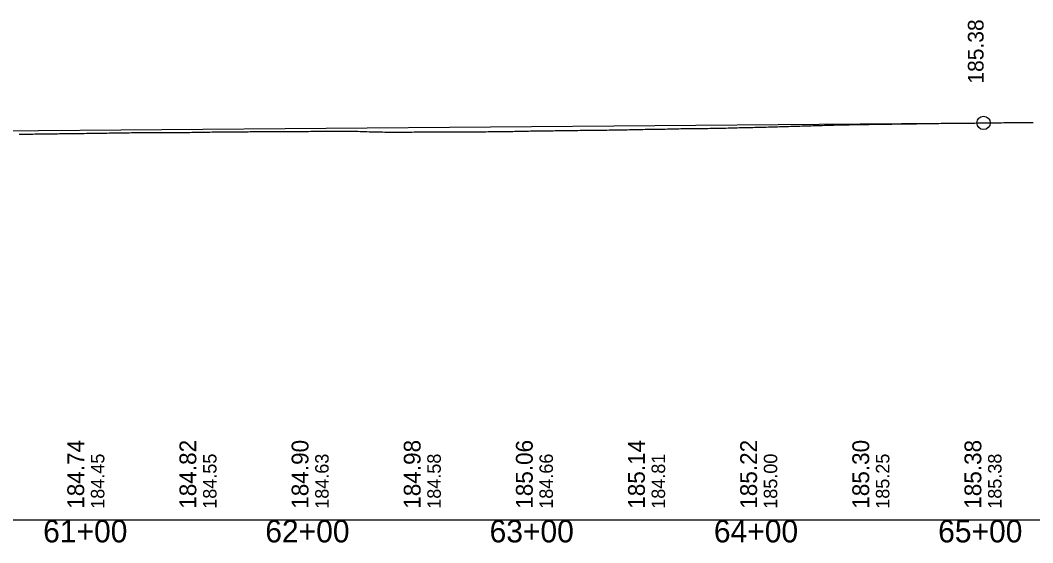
# Model space of a CAD drawing. Extents: x 69 to 2003113, y 512 to 837401.
# Drawn here: x 1893448 to 1893899.5, y 820540 to 820772.8 of the extents above; entities that cross this region are included whole.
import ezdxf

# ---------------------------------------------------------------- set-up
doc = ezdxf.new("R2010")
doc.units = 0
for name, color, linetype in [('BR_BORDER LINES', 7, 'Continuous'), ('BR_CENTER LINE BASELINE', 7, 'Continuous'), ('BR_CONCRETE', 7, 'Continuous'), ('BR_GRID LINES', 7, 'Continuous'), ('BR_TEXT', 7, 'Continuous'), ('RD_HC_Points', 7, 'Continuous'), ('RD_SHT_ID', 7, 'Continuous'), ('RD_SHT_IplotShp', 7, 'Continuous')]:
    doc.layers.add(name, color=color, linetype=linetype)

msp = doc.modelspace()

# ---------------------------------------------------------------- linework, layer by layer
at = {"layer": 'BR_BORDER LINES'}
msp.add_line((1889077.53, 820550.13), (1895477.53, 820550.13), dxfattribs=at)
at = {"layer": 'BR_CENTER LINE BASELINE'}
msp.add_circle((1893877.53, 820727.03), 3, dxfattribs=at)
at = {"layer": 'BR_GRID LINES'}
msp.add_line((1893427.53, 820723.42), (1893877.53, 820727.03), dxfattribs=at)
at = {"layer": 'BR_TEXT'}
for points in [[(1893804.6, 820725.9), (1893805.6, 820725.93), (1893806.6, 820725.97), (1893807.6, 820726), (1893808.6, 820726.03), (1893809.6, 820726.06), (1893810.6, 820726.09), (1893811.6, 820726.11), (1893812.6, 820726.13), (1893813.6, 820726.15), (1893814.6, 820726.17), (1893815.6, 820726.19), (1893816.6, 820726.21), (1893817.6, 820726.23), (1893818.6, 820726.25), (1893819.6, 820726.27), (1893820.6, 820726.29), (1893821.6, 820726.31), (1893822.6, 820726.32), (1893823.6, 820726.34), (1893824.6, 820726.36), (1893825.6, 820726.37), (1893826.6, 820726.38), (1893827.6, 820726.4), (1893828.6, 820726.41), (1893829.6, 820726.43), (1893830.6, 820726.44), (1893831.6, 820726.46), (1893832.6, 820726.47), (1893833.6, 820726.48), (1893834.6, 820726.5), (1893835.6, 820726.51), (1893836.6, 820726.53), (1893837.6, 820726.55), (1893838.6, 820726.56), (1893839.6, 820726.58), (1893840.6, 820726.6), (1893841.6, 820726.61), (1893842.6, 820726.62), (1893843.6, 820726.63), (1893844.6, 820726.65), (1893845.6, 820726.66), (1893846.6, 820726.67), (1893847.6, 820726.68), (1893848.6, 820726.7), (1893849.6, 820726.71), (1893850.6, 820726.72), (1893851.6, 820726.74), (1893852.6, 820726.75), (1893853.6, 820726.76), (1893854.6, 820726.78), (1893855.6, 820726.79), (1893856.6, 820726.81), (1893857.6, 820726.82), (1893858.6, 820726.84), (1893859.6, 820726.85), (1893860.6, 820726.86), (1893861.6, 820726.88), (1893862.6, 820726.89), (1893863.6, 820726.9), (1893864.6, 820726.91), (1893865.6, 820726.92), (1893866.6, 820726.94), (1893867.6, 820726.95), (1893868.6, 820726.95), (1893869.6, 820726.95), (1893870.6, 820726.95), (1893871.6, 820726.96), (1893872.6, 820726.97), (1893873.6, 820726.98), (1893874.6, 820726.99), (1893875.6, 820727.01), (1893876.6, 820727.02), (1893877.6, 820727.03), (1893878.6, 820727.05), (1893879.6, 820727.06), (1893880.6, 820727.07), (1893881.6, 820727.09), (1893882.6, 820727.1), (1893883.6, 820727.11), (1893884.6, 820727.12), (1893885.6, 820727.13), (1893886.6, 820727.14), (1893887.6, 820727.15), (1893888.6, 820727.16), (1893889.6, 820727.16), (1893890.6, 820727.17), (1893891.6, 820727.18), (1893892.6, 820727.19), (1893893.6, 820727.2), (1893894.6, 820727.21), (1893895.6, 820727.22), (1893896.6, 820727.23), (1893897.6, 820727.24), (1893898.6, 820727.26), (1893899.6, 820727.27)], [(1893447.6, 820722), (1893448.6, 820722.02), (1893449.6, 820722.04), (1893450.6, 820722.05), (1893451.6, 820722.05), (1893452.6, 820722.06), (1893453.6, 820722.07), (1893454.6, 820722.09), (1893455.6, 820722.1), (1893456.6, 820722.11), (1893457.6, 820722.13), (1893458.6, 820722.14), (1893459.6, 820722.16), (1893460.6, 820722.17), (1893461.6, 820722.19), (1893462.6, 820722.2), (1893463.6, 820722.22), (1893464.6, 820722.23), (1893465.6, 820722.24), (1893466.6, 820722.25), (1893467.6, 820722.26), (1893468.6, 820722.27), (1893469.6, 820722.29), (1893470.6, 820722.3), (1893471.6, 820722.31), (1893472.6, 820722.32), (1893473.6, 820722.33), (1893474.6, 820722.35), (1893475.6, 820722.36), (1893476.6, 820722.38), (1893477.6, 820722.39), (1893478.6, 820722.41), (1893479.6, 820722.42), (1893480.6, 820722.43), (1893481.6, 820722.45), (1893482.6, 820722.46), (1893483.6, 820722.48), (1893484.6, 820722.49), (1893485.6, 820722.51), (1893486.6, 820722.52), (1893487.6, 820722.53), (1893488.6, 820722.54), (1893489.6, 820722.55), (1893490.6, 820722.56), (1893491.6, 820722.58), (1893492.6, 820722.6), (1893493.6, 820722.61), (1893494.6, 820722.63), (1893495.6, 820722.65), (1893496.6, 820722.66), (1893497.6, 820722.68), (1893498.6, 820722.7), (1893499.6, 820722.71), (1893500.6, 820722.73), (1893501.6, 820722.74), (1893502.6, 820722.75), (1893503.6, 820722.75), (1893504.6, 820722.75)], [(1893504.6, 820722.75), (1893505.6, 820722.75), (1893506.6, 820722.75), (1893507.6, 820722.75), (1893508.6, 820722.75), (1893509.6, 820722.75), (1893510.6, 820722.75), (1893511.6, 820722.76), (1893512.6, 820722.76), (1893513.6, 820722.76), (1893514.6, 820722.76), (1893515.6, 820722.77), (1893516.6, 820722.78), (1893517.6, 820722.78), (1893518.6, 820722.79), (1893519.6, 820722.79), (1893520.6, 820722.8), (1893521.6, 820722.8), (1893522.6, 820722.81), (1893523.6, 820722.82), (1893524.6, 820722.84), (1893525.6, 820722.86), (1893526.6, 820722.87), (1893527.6, 820722.89), (1893528.6, 820722.9), (1893529.6, 820722.92), (1893530.6, 820722.93), (1893531.6, 820722.95), (1893532.6, 820722.96), (1893533.6, 820722.98), (1893534.6, 820722.99), (1893535.6, 820723), (1893536.6, 820723.01), (1893537.6, 820723.03), (1893538.6, 820723.03), (1893539.6, 820723.04), (1893540.6, 820723.05), (1893541.6, 820723.06), (1893542.6, 820723.07), (1893543.6, 820723.08), (1893544.6, 820723.09), (1893545.6, 820723.1), (1893546.6, 820723.11), (1893547.6, 820723.11), (1893548.6, 820723.12), (1893549.6, 820723.12), (1893550.6, 820723.13), (1893551.6, 820723.14), (1893552.6, 820723.15), (1893553.6, 820723.16), (1893554.6, 820723.17), (1893555.6, 820723.18), (1893556.6, 820723.19), (1893557.6, 820723.19), (1893558.6, 820723.2), (1893559.6, 820723.21), (1893560.6, 820723.22), (1893561.6, 820723.23), (1893562.6, 820723.24), (1893563.6, 820723.24), (1893564.6, 820723.25), (1893565.6, 820723.25), (1893566.6, 820723.25), (1893567.6, 820723.25), (1893568.6, 820723.26), (1893569.6, 820723.26), (1893570.6, 820723.26), (1893571.6, 820723.27), (1893572.6, 820723.27), (1893573.6, 820723.27), (1893574.6, 820723.27), (1893575.6, 820723.27), (1893576.6, 820723.27), (1893577.6, 820723.28), (1893578.6, 820723.28), (1893579.6, 820723.28), (1893580.6, 820723.28), (1893581.6, 820723.28), (1893582.6, 820723.28), (1893583.6, 820723.28), (1893584.6, 820723.28), (1893585.6, 820723.28), (1893586.6, 820723.29), (1893587.6, 820723.29), (1893588.6, 820723.29), (1893589.6, 820723.29), (1893590.6, 820723.29), (1893591.6, 820723.29), (1893592.6, 820723.29), (1893593.6, 820723.29), (1893594.6, 820723.29), (1893595.6, 820723.29), (1893596.6, 820723.29), (1893597.6, 820723.29), (1893598.6, 820723.28), (1893599.6, 820723.27), (1893600.6, 820723.26), (1893601.6, 820723.21), (1893602.6, 820723.14), (1893603.6, 820723.07), (1893604.6, 820723)], [(1893604.6, 820723), (1893605.6, 820722.98), (1893606.6, 820722.98), (1893607.6, 820722.98), (1893608.6, 820722.98), (1893609.6, 820722.98), (1893610.6, 820722.97), (1893611.6, 820722.96), (1893612.6, 820722.96), (1893613.6, 820722.95), (1893614.6, 820722.95), (1893615.6, 820722.94), (1893616.6, 820722.94), (1893617.6, 820722.93), (1893618.6, 820722.93), (1893619.6, 820722.93), (1893620.6, 820722.95), (1893621.6, 820722.96), (1893622.6, 820722.97), (1893623.6, 820722.98), (1893624.6, 820722.99), (1893625.6, 820723), (1893626.6, 820723.01), (1893627.6, 820723.02), (1893628.6, 820723.03), (1893629.6, 820723.04), (1893630.6, 820723.05), (1893631.6, 820723.06), (1893632.6, 820723.08), (1893633.6, 820723.08), (1893634.6, 820723.07), (1893635.6, 820723.07), (1893636.6, 820723.07), (1893637.6, 820723.07), (1893638.6, 820723.07), (1893639.6, 820723.07), (1893640.6, 820723.07), (1893641.6, 820723.07), (1893642.6, 820723.07), (1893643.6, 820723.07), (1893644.6, 820723.06), (1893645.6, 820723.06), (1893646.6, 820723.07), (1893647.6, 820723.07), (1893648.6, 820723.08), (1893649.6, 820723.09), (1893650.6, 820723.09), (1893651.6, 820723.1), (1893652.6, 820723.1), (1893653.6, 820723.11), (1893654.6, 820723.12), (1893655.6, 820723.12), (1893656.6, 820723.13), (1893657.6, 820723.13), (1893658.6, 820723.14), (1893659.6, 820723.15), (1893660.6, 820723.15), (1893661.6, 820723.16), (1893662.6, 820723.17), (1893663.6, 820723.19), (1893664.6, 820723.21), (1893665.6, 820723.23), (1893666.6, 820723.25), (1893667.6, 820723.27), (1893668.6, 820723.29), (1893669.6, 820723.3), (1893670.6, 820723.32), (1893671.6, 820723.34), (1893672.6, 820723.36), (1893673.6, 820723.38), (1893674.6, 820723.4), (1893675.6, 820723.42), (1893676.6, 820723.44), (1893677.6, 820723.45), (1893678.6, 820723.46), (1893679.6, 820723.48), (1893680.6, 820723.49), (1893681.6, 820723.51), (1893682.6, 820723.52), (1893683.6, 820723.53), (1893684.6, 820723.54), (1893685.6, 820723.55), (1893686.6, 820723.57), (1893687.6, 820723.58), (1893688.6, 820723.59), (1893689.6, 820723.6), (1893690.6, 820723.62), (1893691.6, 820723.63), (1893692.6, 820723.64), (1893693.6, 820723.65), (1893694.6, 820723.67), (1893695.6, 820723.69), (1893696.6, 820723.71), (1893697.6, 820723.72), (1893698.6, 820723.73), (1893699.6, 820723.74), (1893700.6, 820723.75), (1893701.6, 820723.77), (1893702.6, 820723.78), (1893703.6, 820723.79), (1893704.6, 820723.8)], [(1893704.6, 820723.8), (1893705.6, 820723.81), (1893706.6, 820723.83), (1893707.6, 820723.84), (1893708.6, 820723.85), (1893709.6, 820723.86), (1893710.6, 820723.87), (1893711.6, 820723.89), (1893712.6, 820723.89), (1893713.6, 820723.9), (1893714.6, 820723.91), (1893715.6, 820723.93), (1893716.6, 820723.95), (1893717.6, 820723.98), (1893718.6, 820724), (1893719.6, 820724.02), (1893720.6, 820724.04), (1893721.6, 820724.06), (1893722.6, 820724.09), (1893723.6, 820724.11), (1893724.6, 820724.13), (1893725.6, 820724.15), (1893726.6, 820724.18), (1893727.6, 820724.2), (1893728.6, 820724.22), (1893729.6, 820724.22), (1893730.6, 820724.23), (1893731.6, 820724.23), (1893732.6, 820724.25), (1893733.6, 820724.27), (1893734.6, 820724.29), (1893735.6, 820724.31), (1893736.6, 820724.33), (1893737.6, 820724.35), (1893738.6, 820724.37), (1893739.6, 820724.39), (1893740.6, 820724.41), (1893741.6, 820724.44), (1893742.6, 820724.46), (1893743.6, 820724.48), (1893744.6, 820724.5), (1893745.6, 820724.51), (1893746.6, 820724.53), (1893747.6, 820724.54), (1893748.6, 820724.55), (1893749.6, 820724.56), (1893750.6, 820724.57), (1893751.6, 820724.58), (1893752.6, 820724.58), (1893753.6, 820724.59), (1893754.6, 820724.6), (1893755.6, 820724.61), (1893756.6, 820724.62), (1893757.6, 820724.62), (1893758.6, 820724.63), (1893759.6, 820724.65), (1893760.6, 820724.68), (1893761.6, 820724.71), (1893762.6, 820724.74), (1893763.6, 820724.77), (1893764.6, 820724.8), (1893765.6, 820724.83), (1893766.6, 820724.86), (1893767.6, 820724.89), (1893768.6, 820724.92), (1893769.6, 820724.95), (1893770.6, 820724.98), (1893771.6, 820725.01), (1893772.6, 820725.02), (1893773.6, 820725.03), (1893774.6, 820725.04), (1893775.6, 820725.06), (1893776.6, 820725.09), (1893777.6, 820725.12), (1893778.6, 820725.14), (1893779.6, 820725.17), (1893780.6, 820725.2), (1893781.6, 820725.22), (1893782.6, 820725.25), (1893783.6, 820725.28), (1893784.6, 820725.31), (1893785.6, 820725.35), (1893786.6, 820725.39), (1893787.6, 820725.42), (1893788.6, 820725.44), (1893789.6, 820725.46), (1893790.6, 820725.48), (1893791.6, 820725.51), (1893792.6, 820725.54), (1893793.6, 820725.57), (1893794.6, 820725.6), (1893795.6, 820725.63), (1893796.6, 820725.65), (1893797.6, 820725.68), (1893798.6, 820725.71), (1893799.6, 820725.74), (1893800.6, 820725.77), (1893801.6, 820725.81), (1893802.6, 820725.84), (1893803.6, 820725.87), (1893804.6, 820725.9)]]:
    msp.add_lwpolyline(points, dxfattribs=at)

# ---------------------------------------------------------------- texts
at = {"layer": 'BR_CONCRETE'}
for s, p in [('184.45', (1893485.53, 820555.13)), ('184.55', (1893535.53, 820555.13)), ('184.63', (1893585.53, 820555.13)), ('184.58', (1893635.53, 820555.13)), ('184.66', (1893685.53, 820555.13)), ('184.81', (1893735.53, 820555.13)), ('185.00', (1893785.53, 820555.13)), ('185.25', (1893835.53, 820555.13)), ('185.38', (1893885.53, 820555.13))]:
    msp.add_text(s, height=6, rotation=90, dxfattribs=at).set_placement(p)
at = {"layer": 'RD_HC_Points'}
for s, p in [('184.74', (1893476.53, 820555.13)), ('184.82', (1893526.53, 820555.13)), ('184.90', (1893576.53, 820555.13)), ('184.98', (1893626.53, 820555.13)), ('185.06', (1893676.53, 820555.13)), ('185.14', (1893726.53, 820555.13)), ('185.22', (1893776.53, 820555.13)), ('185.30', (1893826.53, 820555.13)), ('185.38', (1893876.53, 820555.13))]:
    msp.add_text(s, height=7.5, rotation=90, dxfattribs=at).set_placement(p)
at = {"layer": 'RD_SHT_ID'}
for s, p in [('61+00', (1893458.25, 820540.13)), ('62+00', (1893557.29, 820540.13)), ('63+00', (1893657.29, 820540.13)), ('64+00', (1893757.29, 820540.13)), ('65+00', (1893857.29, 820540.13))]:
    msp.add_text(s, height=10, dxfattribs=at).set_placement(p)
at = {"layer": 'RD_SHT_IplotShp'}
msp.add_text('185.38', height=7, rotation=90, dxfattribs=at).set_placement((1893877.53, 820744.53))

doc.saveas('drawing.dxf')
